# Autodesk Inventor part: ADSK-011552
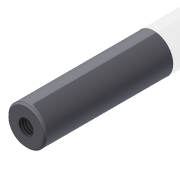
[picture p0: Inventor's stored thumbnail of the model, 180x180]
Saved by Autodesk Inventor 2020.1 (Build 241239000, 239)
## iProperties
Created: 2000-02
Part Number: ADSK-011552
Material: Pearson HRS
Document SubType Name: Modeling
Designer: glanglot
Density: 7.83 g/cm^3
Appearance: Métal - Acier
Mass: 94.9765 g
Surface Area: 39.4333 cm^2
Volume: 12.1298 cm^3
Control State: 0
Checked Out: False
Master: False
Shininess: 0.0
Length Units: 11269
Angle Units: 11279
Time Units: 11290
Mass Units: 11283
Length Display Precision: 3
Angle Display Precision: 2
Compacted: True
Cutlength: 3.38
Material Desc: ROUND,CD 1018,1.0000 DIA
Material_Number: A084576
Dimensions: 17x17x57 mm
Mass: 0,095 kg
DocNumber: ADSK-011552.ipt
Folder: 01 - Themengebiete\Simplification\01 - Packaging machine\
VDS_Category: 3D Komponenten
Density: 0.0
Volumn: 0.0
Area: 0.0
PropertySet Name: Model Information
Author: glanglot
Revision Number: -
Title: pin
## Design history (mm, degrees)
node "Solide1"
  node "Extrusion1" dims "d1" = 57, "d2" = 0
  node "Chamfer1" dims "d3" = 0.75, "d4" = 0.75, "d5" = 45 deg
sketch "Sketch1"
  geometry: C1 r 8.5 at (0, 0); 1 further point
  constraints: 1 centre point, 1 coincident
  dimensions: "d0" = 17 diameter of C1
sketch "Skizze2"
  geometry: C1 r 8.5 at (0, 0) reference; 2 further points
  constraints: 1 coincident
hole "Bohrung1" sketch "Skizze2" diameter "d6" = 6.647; stored, may be unused: countersink angle "d10" = 90 deg, drill point angle "d12" = 118 deg; dims "d7" = 16, "d8" = 10, "d9" = 5.7, "d11" = 22.2
node "Corps solides"
node "Corps surfaciques"
